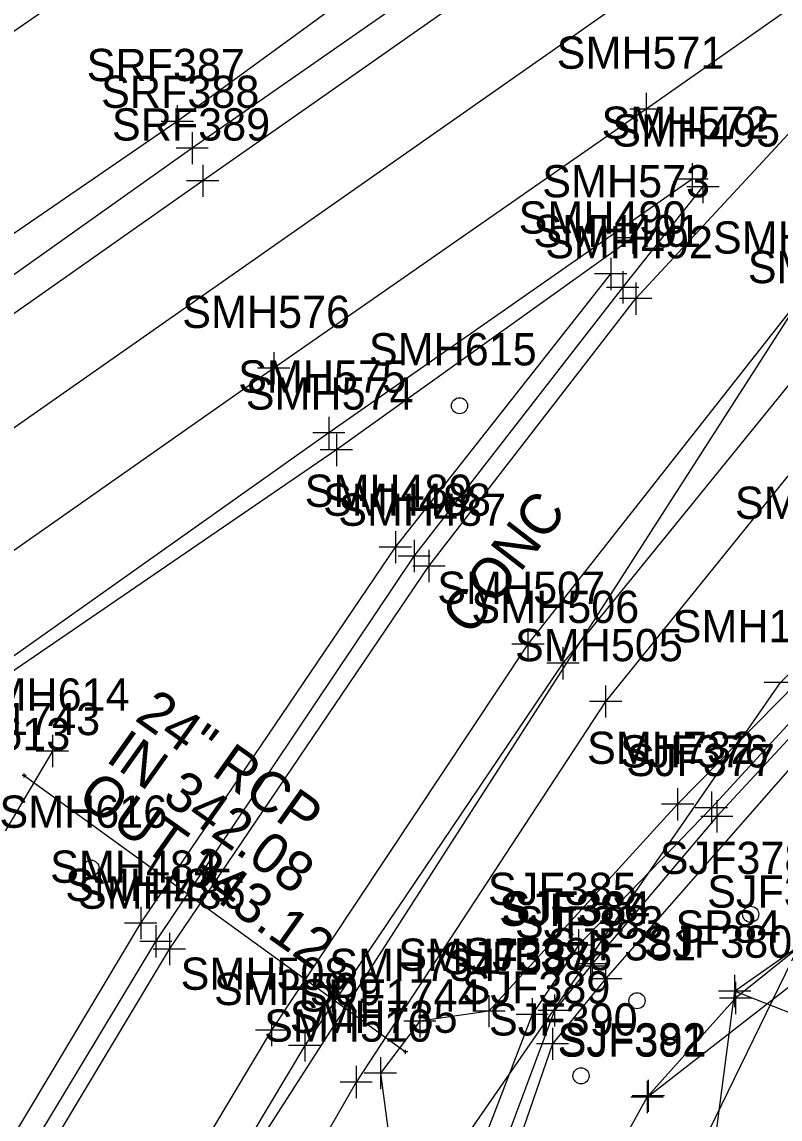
# Model space of a CAD drawing. Extents: x 941041 to 969446, y 397014 to 416764.
# Drawn here: x 952280.5 to 952374.6, y 403399.5 to 403535.6 of the extents above; entities that cross this region are included whole.
import ezdxf

# ---------------------------------------------------------------- set-up
doc = ezdxf.new("R2010")
doc.units = 0
for name, color, linetype in [('SURVEY - DRAINAGE - Area Shapes', 7, 'Continuous'), ('SURVEY - DRAINAGE - Pipes and Culverts', 7, 'Continuous'), ('SURVEY - DRAINAGE - Pipes and Culverts - Points - Locators', 7, 'Continuous'), ('SURVEY - DRAINAGE - Pipes and Culverts - Points - Numbers', 7, 'Continuous'), ('SURVEY - DRAINAGE - Pipes and Culverts Text', 7, 'Continuous'), ('SURVEY - DTM - Breaklines', 7, 'Continuous'), ('SURVEY - DTM - Breaklines - Points - Locators', 7, 'Continuous'), ('SURVEY - DTM - Breaklines - Points - Numbers', 7, 'Continuous'), ('SURVEY - DTM - Spot Points - Locators', 7, 'Continuous'), ('SURVEY - DTM - Spot Points - Point Numbers', 7, 'Continuous'), ('SURVEY - DTM GRAPHICS - Boundary Line', 7, 'Continuous'), ('SURVEY - NON-TRANSPORTATION - Features', 7, 'Continuous'), ('SURVEY - NON-TRANSPORTATION - Features - Points - Locators', 7, 'Continuous'), ('SURVEY - NON-TRANSPORTATION - Features - Points - Numbers', 7, 'Continuous'), ('SURVEY - PROPERTY - ROW Lines', 7, 'Continuous'), ('SURVEY - PROPERTY - ROW Lines - Points - Locators', 7, 'Continuous'), ('SURVEY - PROPERTY - ROW Lines - Points - Numbers', 7, 'Continuous'), ('SURVEY - PROPERTY - Station and Offset Flags', 7, 'Continuous'), ('SURVEY - TRANSPORTATION - Features', 7, 'Continuous'), ('SURVEY - TRANSPORTATION - Features - Points - Locators', 7, 'Continuous'), ('SURVEY - TRANSPORTATION - Features - Points - Numbers', 7, 'Continuous'), ('SURVEY - TRANSPORTATION - Features Text', 7, 'Continuous'), ('SURVEY - TRANSPORTATION - Roads', 7, 'Continuous'), ('SURVEY - TRANSPORTATION - Roads - Points - Locators', 7, 'Continuous'), ('SURVEY - TRANSPORTATION - Roads - Points - Numbers', 7, 'Continuous'), ('SURVEY - VEGETATION - Features - Points - Locators', 7, 'Continuous'), ('SURVEY - VEGETATION - Features - Points - Numbers', 7, 'Continuous'), ('SURVEY - VEGETATION - Features with Text', 7, 'Continuous')]:
    doc.layers.add(name, color=color, linetype=linetype)

msp = doc.modelspace()

# ---------------------------------------------------------------- linework, layer by layer
at = {"layer": 'SURVEY - DRAINAGE - Area Shapes'}
for points in [[(950765.73, 402528.11), (950855.07, 402487.28), (951056.09, 402625.14), (951609.08, 403015.7), (952524.78, 403657.05), (952475.83, 403724.71)], [(952524.78, 403657.05), (952492.12, 403619.04), (952377.47, 403501.88), (952288.71, 403363.65), (952144.73, 403130.14), (952066.04, 403042.14), (951972.88, 402968.67), (951909.7, 402961.24), (951854.04, 402976.32), (951847.06, 402862.63), (951840.23, 402758.71), (951891.23, 402760.8), (952228.34, 402790.58), (952361.3, 402834.13), (953526.16, 402149.04), (954070.26, 402059.9)]]:
    msp.add_lwpolyline(points, dxfattribs=at)
at = {"layer": 'SURVEY - DRAINAGE - Pipes and Culverts'}
msp.add_line((952280.83, 403442.16), (952328.13, 403407.88), dxfattribs=at)
at = {"layer": 'SURVEY - DRAINAGE - Pipes and Culverts - Points - Locators'}
for p, q in [((952281.08, 403442.16), (952280.58, 403442.16)), ((952280.83, 403441.91), (952280.83, 403442.41)), ((952280.83, 403442.16), (952280.83, 403442.16)), ((952280.83, 403442.16), (952280.83, 403442.16)), ((952328.13, 403407.63), (952328.13, 403408.13)), ((952328.38, 403407.88), (952327.88, 403407.88)), ((952328.13, 403407.88), (952328.13, 403407.88)), ((952328.13, 403407.88), (952328.13, 403407.88))]:
    msp.add_line(p, q, dxfattribs=at)
at = {"layer": 'SURVEY - DTM - Breaklines'}
for points in [[(952736.12, 403724.5), (952691.91, 403690.39), (952652.91, 403661.72), (952597.79, 403620.04), (952558.5, 403596.43), (952540.39, 403606.94), (952539.83, 403606.39), (952554.53, 403592.08), (952552.67, 403578.76), (952522.24, 403557.97), (952459.92, 403516.62), (952405.87, 403481.47), (952366.05, 403438.15), (952349.58, 403421.1), (952343.82, 403412.52), (952314.34, 403335.84)], [(952737.07, 403722.49), (952692.53, 403689.24), (952653.03, 403660.5), (952601.74, 403618.14), (952557.82, 403590.87), (952555.49, 403578.9), (952523.84, 403556.42), (952459.22, 403512.77), (952406.44, 403479.97), (952366.72, 403437.08), (952351.28, 403418.78), (952351.07, 403418.51), (952346.58, 403413.01), (952317.46, 403334.95)], [(952745.6, 403709.26), (952701.3, 403681.67), (952659.46, 403650.99), (952608.65, 403618.13), (952559.91, 403588.24), (952555.32, 403575.05), (952528.03, 403556.34), (952406.89, 403478.52), (952352.92, 403416.94), (952346.34, 403408.88), (952320.69, 403334.64)], [(952485.25, 403679.95), (952429.13, 403639.43), (952382.71, 403607.61), (952334.17, 403572.43), (952289.83, 403541.57), (952238.45, 403506.07), (952195.26, 403475.23), (952146.22, 403440.76), (952099.32, 403409.75), (952050.92, 403375.53), (952007.43, 403342.26), (951963.47, 403311.23), (951910.97, 403277.41), (951839.65, 403222.38)], [(952450.65, 403522.86), (952407.71, 403486.54), (952386.56, 403463.73), (952361.86, 403438.59), (952338.46, 403412.93), (952329.89, 403411.67), (952325, 403405.24), (952327.02, 403389.98), (952317.62, 403360.79), (952303.59, 403327.17), (952284.04, 403302.52), (952269.86, 403290.27), (952268.05, 403273.15), (952243.67, 403236.98), (952228.06, 403211.3)], [(952284.32, 403445.19), (952160.86, 403236.96), (952125.87, 403192.45), (952077.94, 403136.62), (952039.19, 403098.25), (952006.25, 403068.24), (951969.46, 403038.09), (951934.26, 403008.18), (951912.19, 402997.34), (951900.8, 403002.03), (951909.31, 403040.46), (951919.74, 403082.57), (951927.08, 403105.04), (951926.24, 403141.28), (951910.03, 403171.31), (951930.4, 403184.14)]]:
    msp.add_lwpolyline(points, dxfattribs=at)
at = {"layer": 'SURVEY - DTM - Breaklines - Points - Locators'}
for p, q in [((952284.32, 403447.19), (952284.32, 403443.19)), ((952286.32, 403445.19), (952282.32, 403445.19)), ((952361.86, 403440.59), (952361.86, 403436.59)), ((952366.05, 403440.15), (952366.05, 403436.15)), ((952363.86, 403438.59), (952359.86, 403438.59)), ((952368.05, 403438.15), (952364.05, 403438.15)), ((952366.72, 403439.08), (952366.72, 403435.08)), ((952368.72, 403437.08), (952364.72, 403437.08)), ((952349.58, 403423.1), (952349.58, 403419.1)), ((952351.58, 403421.1), (952347.58, 403421.1)), ((952351.07, 403420.51), (952351.07, 403416.51)), ((952351.28, 403420.78), (952351.28, 403416.78)), ((952352.92, 403418.94), (952352.92, 403414.94)), ((952353.07, 403418.51), (952349.07, 403418.51)), ((952353.28, 403418.78), (952349.28, 403418.78)), ((952354.92, 403416.94), (952350.92, 403416.94)), ((952338.46, 403414.93), (952338.46, 403410.93)), ((952346.58, 403415.01), (952346.58, 403411.01)), ((952329.89, 403413.67), (952329.89, 403409.67)), ((952343.82, 403414.52), (952343.82, 403410.52)), ((952340.46, 403412.93), (952336.46, 403412.93)), ((952345.82, 403412.52), (952341.82, 403412.52)), ((952348.58, 403413.01), (952344.58, 403413.01)), ((952331.89, 403411.67), (952327.89, 403411.67)), ((952346.34, 403410.88), (952346.34, 403406.88)), ((952348.34, 403408.88), (952344.34, 403408.88)), ((952325, 403407.24), (952325, 403403.24)), ((952327, 403405.24), (952323, 403405.24))]:
    msp.add_line(p, q, dxfattribs=at)
at = {"layer": 'SURVEY - DTM - Spot Points - Locators'}
for centre in [(952334.81, 403488.01), (952289.1, 403430.67), (952370.92, 403424.94), (952356.82, 403414.22), (952349.88, 403404.91)]:
    msp.add_circle(centre, 1, dxfattribs=at)
at = {"layer": 'SURVEY - DTM GRAPHICS - Boundary Line'}
msp.add_lwpolyline([(952035.48, 402957.27), (952071.58, 402994.94), (952104.2, 403029.37), (952152.09, 403078.34), (952185.06, 403125.25), (952207.21, 403161.01), (952229.39, 403196.73), (952259.83, 403237.91), (952277.71, 403262.68), (952290.35, 403264.85), (952296.52, 403262.95), (952302.37, 403268.11), (952305.43, 403292.27), (952320.69, 403334.64), (952358.07, 403402.28), (952434.4, 403461.68), (952438.94, 403466.81), (952457.13, 403479.78), (952544.24, 403540.36), (952613.11, 403589.47), (952670.27, 403628.77)], dxfattribs=at)
at = {"layer": 'SURVEY - NON-TRANSPORTATION - Features'}
msp.add_lwpolyline([(952376.77, 403420.76), (952369.04, 403414.55), (952358.22, 403402.43), (952358.07, 403402.28)], dxfattribs=at)
at = {"layer": 'SURVEY - NON-TRANSPORTATION - Features - Points - Locators'}
for p, q in [((952369.04, 403416.55), (952369.04, 403412.55)), ((952371.04, 403414.55), (952367.04, 403414.55)), ((952358.07, 403404.28), (952358.07, 403400.28)), ((952358.22, 403404.43), (952358.22, 403400.43)), ((952360.07, 403402.28), (952356.07, 403402.28)), ((952360.22, 403402.43), (952356.22, 403402.43))]:
    msp.add_line(p, q, dxfattribs=at)
at = {"layer": 'SURVEY - PROPERTY - ROW Lines'}
for q in [(953970.44, 404538.71), (952337.2, 403173.31)]:
    msp.add_line((952368.92, 403415.42), q, dxfattribs=at)
at = {"layer": 'SURVEY - PROPERTY - ROW Lines - Points - Locators'}
for p, q in [((952368.92, 403417.42), (952368.92, 403413.42)), ((952370.92, 403415.42), (952366.92, 403415.42))]:
    msp.add_line(p, q, dxfattribs=at)
at = {"layer": 'SURVEY - PROPERTY - Station and Offset Flags'}
msp.add_lwpolyline([(952393.3, 403405.83), (952368.92, 403415.42)], dxfattribs=at)
at = {"layer": 'SURVEY - TRANSPORTATION - Features'}
for points in [[(952622.56, 403749.53), (952577.8, 403717.92), (952532.08, 403686.84), (952486.03, 403653.05), (952440.27, 403622.51), (952394.74, 403590.13), (952344.15, 403555.61), (952299.81, 403523.27), (952250.2, 403489.24), (952206.86, 403458.08), (952156.3, 403423.75), (952110.49, 403390.56), (952062.35, 403358.41), (952017.69, 403325.18), (951971.92, 403293.52), (951916.96, 403254.99), (951879.97, 403228.71), (951856.72, 403212.68)], [(952463.7, 403566.84), (952424.44, 403532.16), (952386.95, 403493.43), (952352.93, 403451.33), (952321.99, 403404.14), (952295.3, 403357.63), (952270.34, 403313.98), (952241.93, 403265.74), (952208.83, 403217.23), (952179.84, 403174.88), (952146.26, 403127.61), (952109.6, 403083.06), (952068.28, 403040.45), (952026.52, 403003), (951981.94, 402968.99), (951929.76, 402929.79), (951899.74, 402893.98), (951883.92, 402865.94), (951878.37, 402845.72), (951874.04, 402827.93), (951876.74, 402809.53), (951887.15, 402791.78)], [(952356.31, 403508.85), (952319.54, 403482.53), (952271.2, 403449.46), (952218.02, 403412.1), (952168.51, 403377.19), (952118.64, 403342.5), (952070.41, 403308.53), (952018.6, 403272.33), (951969.85, 403238.11), (951920.07, 403203.33), (951882.16, 403176.11), (951845.47, 403150.79)], [(951876.39, 403112.43), (951877.41, 403108.88), (951874.65, 403046.53), (951875.12, 403005.5), (951885.48, 402985.02), (951901.34, 402976.24), (951925.41, 402975.64), (951956.41, 402989.5), (952002.91, 403023.51), (952035.36, 403050.69), (952073.7, 403089.73), (952112.45, 403134.55), (952147.27, 403180.21), (952178.93, 403228.56), (952206.23, 403275.42), (952237.69, 403327.41), (952265.08, 403373.37), (952295.28, 403423.85), (952326.86, 403470.47), (952353.56, 403504.36)]]:
    msp.add_lwpolyline(points, dxfattribs=at)
at = {"layer": 'SURVEY - TRANSPORTATION - Features - Points - Locators'}
for p, q in [((952299.81, 403525.27), (952299.81, 403521.27)), ((952301.81, 403523.27), (952297.81, 403523.27)), ((952356.31, 403510.85), (952356.31, 403506.85)), ((952358.31, 403508.85), (952354.31, 403508.85)), ((952353.56, 403506.36), (952353.56, 403502.36)), ((952355.56, 403504.36), (952351.56, 403504.36)), ((952319.54, 403484.53), (952319.54, 403480.53)), ((952321.54, 403482.53), (952317.54, 403482.53)), ((952326.86, 403472.47), (952326.86, 403468.47)), ((952328.86, 403470.47), (952324.86, 403470.47)), ((952352.93, 403453.33), (952352.93, 403449.33)), ((952354.93, 403451.33), (952350.93, 403451.33)), ((952295.28, 403425.85), (952295.28, 403421.85)), ((952297.28, 403423.85), (952293.28, 403423.85)), ((952321.99, 403406.14), (952321.99, 403402.14)), ((952323.99, 403404.14), (952319.99, 403404.14))]:
    msp.add_line(p, q, dxfattribs=at)
at = {"layer": 'SURVEY - TRANSPORTATION - Roads'}
for points in [[(952625.22, 403746.95), (952579.91, 403715.1), (952534.83, 403683.49), (952487.43, 403650.41), (952442.83, 403619.09), (952396.91, 403586.46), (952346.61, 403551.28), (952301.65, 403519.95), (952253.11, 403485.53), (952208.83, 403454.47), (952159.44, 403419.8), (952112.68, 403387.11), (952066.16, 403354.45), (952019.33, 403321.73), (951973.66, 403289.75), (951918.65, 403251.32), (951882.81, 403225.68), (951856.94, 403208.02)], [(952627.47, 403743.75), (952581.75, 403711.66), (952537.07, 403680.23), (952488.75, 403646.32), (952445.47, 403615.87), (952397.1, 403581.89), (952349.33, 403548.4), (952302.96, 403515.9), (952255.29, 403482.36), (952210.22, 403450.79), (952161.93, 403416.95), (952113.95, 403383.26), (952068.49, 403351.38), (952021.19, 403318.27), (951975.59, 403286.18), (951920.11, 403247.28), (951884.29, 403222.24), (951858.06, 403203.77)], [(952447.34, 403587.64), (952403.74, 403556.93), (952357.95, 403524.8), (952311.77, 403492.65), (952264.09, 403459.22), (952211.18, 403421.94), (952159.19, 403385.58), (952111.45, 403351.91), (952063.96, 403319.03), (952011.56, 403282.13), (951962.38, 403247.78), (951912.18, 403212.48), (951876.49, 403187.38), (951846.26, 403165.91)], [(951865.8, 403008.31), (951866.15, 403005.56), (951870.88, 402986.54), (951882.98, 402972.26), (951909.7, 402961.24), (951937.83, 402969.25), (951963.44, 402985.92), (951994.04, 403009.28), (952032.28, 403040.88), (952076.34, 403084), (952116.65, 403130.24), (952151.69, 403177.54), (952182.07, 403225.35), (952210.54, 403273.2), (952241.14, 403324.77), (952269.17, 403371.23), (952298.83, 403420.63), (952331.01, 403468.12), (952356.67, 403501.3), (952395.48, 403543.21), (952445.2, 403585.68)], [(952455.35, 403576.86), (952415.67, 403541.68), (952377.47, 403501.88), (952343.29, 403458.44), (952311.51, 403410.58), (952284.76, 403365.84), (952258.41, 403322.08), (952230.37, 403275.05), (952199.68, 403223.63), (952172.53, 403180.11), (952139.24, 403133), (952102.73, 403089.01), (952061.21, 403046.18), (952018.15, 403007.86), (951970.15, 402971.5), (951933.15, 402944.53), (951910.93, 402922.73), (951891.55, 402898.16), (951877.55, 402875.89), (951859.36, 402837.53)], [(952459.67, 403571.86), (952420.1, 403537.84), (952381.8, 403498.21), (952347.63, 403456.07), (952315.62, 403408.68), (952288.71, 403363.65), (952262.47, 403320.1), (952234.46, 403272.79), (952203.33, 403221.24), (952176.72, 403177.53), (952143.38, 403130.61), (952105.84, 403085.28), (952064.68, 403043.34), (952020.29, 403004.45), (951972.88, 402968.67), (951935.5, 402941.59), (951914.66, 402920.84), (951894.55, 402896.1), (951881.05, 402875.02), (951865.64, 402835.43)], [(952363.66, 403516.11), (952318.6, 403484.64), (952270.5, 403450.6), (952217.03, 403413.11), (952165.82, 403377.48), (952117.66, 403343.68), (952069.64, 403309.92), (952017.59, 403273.34), (951968.61, 403239.23), (951919.39, 403204.95), (951881.03, 403178.29), (951848.45, 403157.23)], [(951868.66, 403020.4), (951868.75, 403005.58), (951874.6, 402988.78), (951885.58, 402976.09), (951909.34, 402966.72), (951936.24, 402972.08), (951962.8, 402986.78), (951993.75, 403010.02), (952030.85, 403042.24), (952075.7, 403086.1), (952114.61, 403131.25), (952149.56, 403178.29), (952180.65, 403227.07), (952208.11, 403274.26), (952239.48, 403325.89), (952267.27, 403372.02), (952297.15, 403421.58), (952329.18, 403469.36), (952355.05, 403502.68), (952364.99, 403515.15)]]:
    msp.add_lwpolyline(points, dxfattribs=at)
at = {"layer": 'SURVEY - TRANSPORTATION - Roads - Points - Locators'}
for p, q in [((952357.95, 403526.8), (952357.95, 403522.8)), ((952359.95, 403524.8), (952355.95, 403524.8)), ((952301.65, 403521.95), (952301.65, 403517.95)), ((952303.65, 403519.95), (952299.65, 403519.95)), ((952302.96, 403517.9), (952302.96, 403513.9)), ((952363.66, 403518.11), (952363.66, 403514.11)), ((952364.99, 403517.15), (952364.99, 403513.15)), ((952304.96, 403515.9), (952300.96, 403515.9)), ((952365.66, 403516.11), (952361.66, 403516.11)), ((952366.99, 403515.15), (952362.99, 403515.15)), ((952355.05, 403504.68), (952355.05, 403500.68)), ((952356.67, 403503.3), (952356.67, 403499.3)), ((952357.05, 403502.68), (952353.05, 403502.68)), ((952358.67, 403501.3), (952354.67, 403501.3)), ((952311.77, 403494.65), (952311.77, 403490.65)), ((952313.77, 403492.65), (952309.77, 403492.65)), ((952318.6, 403486.64), (952318.6, 403482.64)), ((952320.6, 403484.64), (952316.6, 403484.64)), ((952329.18, 403471.36), (952329.18, 403467.36)), ((952331.18, 403469.36), (952327.18, 403469.36)), ((952331.01, 403470.12), (952331.01, 403466.12)), ((952333.01, 403468.12), (952329.01, 403468.12)), ((952343.29, 403460.44), (952343.29, 403456.44)), ((952345.29, 403458.44), (952341.29, 403458.44)), ((952347.63, 403458.07), (952347.63, 403454.07)), ((952349.63, 403456.07), (952345.63, 403456.07)), ((952297.15, 403423.58), (952297.15, 403419.58)), ((952298.83, 403422.63), (952298.83, 403418.63)), ((952299.15, 403421.58), (952295.15, 403421.58)), ((952300.83, 403420.63), (952296.83, 403420.63)), ((952311.51, 403412.58), (952311.51, 403408.58)), ((952313.51, 403410.58), (952309.51, 403410.58)), ((952315.62, 403410.68), (952315.62, 403406.68)), ((952317.62, 403408.68), (952313.62, 403408.68))]:
    msp.add_line(p, q, dxfattribs=at)
at = {"layer": 'SURVEY - VEGETATION - Features - Points - Locators'}
msp.add_line((952376.61, 403453.68), (952372.61, 403453.68), dxfattribs=at)
at = {"layer": 'SURVEY - VEGETATION - Features with Text'}
msp.add_lwpolyline([(953978, 404545.36), (952376.77, 403420.76), (952302.37, 403268.11), (952235, 403233.08), (952263.4, 403271.68), (952268, 403292.82), (952313.09, 403364.79), (952374.61, 403453.68), (952430.54, 403509.23), (952518.9, 403556.35), (952567.29, 403603.14), (952615.41, 403645.7), (952663.71, 403647.1)], dxfattribs=at)

# ---------------------------------------------------------------- texts
at = {"layer": 'SURVEY - DRAINAGE - Pipes and Culverts - Points - Numbers'}
for s, p in [('SRF1743', (952267.64, 403447.16)), ('SRF1744', (952314.94, 403412.88))]:
    msp.add_text(s, height=4, dxfattribs=at).set_placement(p)
at = {"layer": 'SURVEY - DRAINAGE - Pipes and Culverts Text'}
for s, p in [('24" RCP', (952294.38, 403449.09)), ('IN 342.08', (952290.78, 403444.02)), ('OUT 343.12', (952287.18, 403438.95))]:
    msp.add_text(s, height=4.998, rotation=324.6149, dxfattribs=at).set_placement(p)
at = {"layer": 'SURVEY - DTM - Breaklines - Points - Numbers'}
for s, p in [('SMH731', (952368.97, 403473.98)), ('SMH614', (952273.08, 403450.19)), ('SMH613', (952265.72, 403445.29)), ('SMH732', (952350.63, 403443.59)), ('SJF376', (952354.7, 403443.15)), ('SJF377', (952355.48, 403442.08)), ('SJF385', (952338.34, 403426.1)), ('SJF386', (952339.72, 403423.51)), ('SJF384', (952340.04, 403423.78)), ('SJF383', (952341.68, 403421.94)), ('SMH733', (952327.22, 403417.93)), ('SJF388', (952335.3, 403418.01)), ('SMH734', (952318.65, 403416.67)), ('SJF387', (952332.58, 403417.52)), ('SJF389', (952335.08, 403413.88)), ('SMH735', (952313.76, 403410.24))]:
    msp.add_text(s, height=4, dxfattribs=at).set_placement(p)
at = {"layer": 'SURVEY - DTM - Spot Points - Point Numbers'}
for s, p in [('SMH615', (952323.57, 403493.01)), ('SMH616', (952277.75, 403435.67)), ('SJF378', (952359.64, 403429.94)), ('SJF381', (952345.73, 403419.22)), ('SJF390', (952338.46, 403409.91))]:
    msp.add_text(s, height=4, dxfattribs=at).set_placement(p)
at = {"layer": 'SURVEY - NON-TRANSPORTATION - Features - Points - Numbers'}
for s, p in [('SJF379', (952365.52, 403425.76)), ('SJF380', (952357.63, 403419.55)), ('SJF382', (952346.98, 403407.43)), ('SJF391', (952346.99, 403407.28))]:
    msp.add_text(s, height=4, dxfattribs=at).set_placement(p)
at = {"layer": 'SURVEY - PROPERTY - ROW Lines - Points - Numbers'}
msp.add_text('SP84', height=4, dxfattribs=at).set_placement((952361.59, 403421.42))
at = {"layer": 'SURVEY - TRANSPORTATION - Features - Points - Numbers'}
for s, p in [('SRF387', (952288.57, 403528.27)), ('SMH573', (952345.07, 403513.85)), ('SMH490', (952342.14, 403509.36)), ('SMH574', (952308.3, 403487.53)), ('SMH489', (952315.61, 403475.47)), ('SMH505', (952341.69, 403456.33)), ('SMH484', (952284.04, 403428.85)), ('SMH510', (952310.58, 403409.14))]:
    msp.add_text(s, height=4, dxfattribs=at).set_placement(p)
at = {"layer": 'SURVEY - TRANSPORTATION - Features Text'}
msp.add_text('CONC', height=5, rotation=52.3058, dxfattribs=at).set_placement((952336.19, 403459.28))
at = {"layer": 'SURVEY - TRANSPORTATION - Roads - Points - Numbers'}
for s, p in [('SMH571', (952346.86, 403529.8)), ('SRF388', (952290.36, 403524.95)), ('SMH572', (952352.42, 403521.11)), ('SRF389', (952291.7, 403520.9)), ('SMH495', (952353.75, 403520.15)), ('SMH491', (952343.97, 403507.68)), ('SMH492', (952345.43, 403506.3)), ('SMH502', (952366.24, 403506.88)), ('SMH502', (952366.24, 403506.88)), ('SMH503', (952370.56, 403503.21)), ('SMH576', (952300.42, 403497.65)), ('SMH575', (952307.36, 403489.64)), ('SMH488', (952317.9, 403474.36)), ('SMH487', (952319.77, 403473.12)), ('SMH507', (952332.05, 403463.44)), ('SMH506', (952336.28, 403461.07)), ('SMH485', (952285.91, 403426.58)), ('SMH486', (952287.48, 403425.63)), ('SMH508', (952300.22, 403415.58)), ('SMH509', (952304.37, 403413.68))]:
    msp.add_text(s, height=4, dxfattribs=at).set_placement(p)
at = {"layer": 'SURVEY - VEGETATION - Features - Points - Numbers'}
msp.add_text('SMH1390', height=4, dxfattribs=at).set_placement((952361.24, 403458.68))

doc.saveas('drawing.dxf')
